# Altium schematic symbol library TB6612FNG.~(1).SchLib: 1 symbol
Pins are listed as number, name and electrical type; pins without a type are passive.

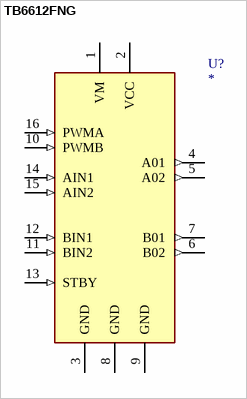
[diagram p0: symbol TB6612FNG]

## TB6612FNG
designator U?
TB6612FNG Dual Motor Driver Module; MP: ROB-14450; MF: SparkFun Electronics
footprint TB6612FNG
pins: 1 VM (power), 2 VCC (power), 3 GND (power), 4 A01 (out), 5 A02 (out), 6 B02 (out), 7 B01 (out), 8 GND (power), 9 GND (power), 10 PWMB (in), 11 BIN2 (in), 12 BIN1 (in), 13 STBY (in), 14 AIN1 (in), 15 AIN2 (in), 16 PWMA (in)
